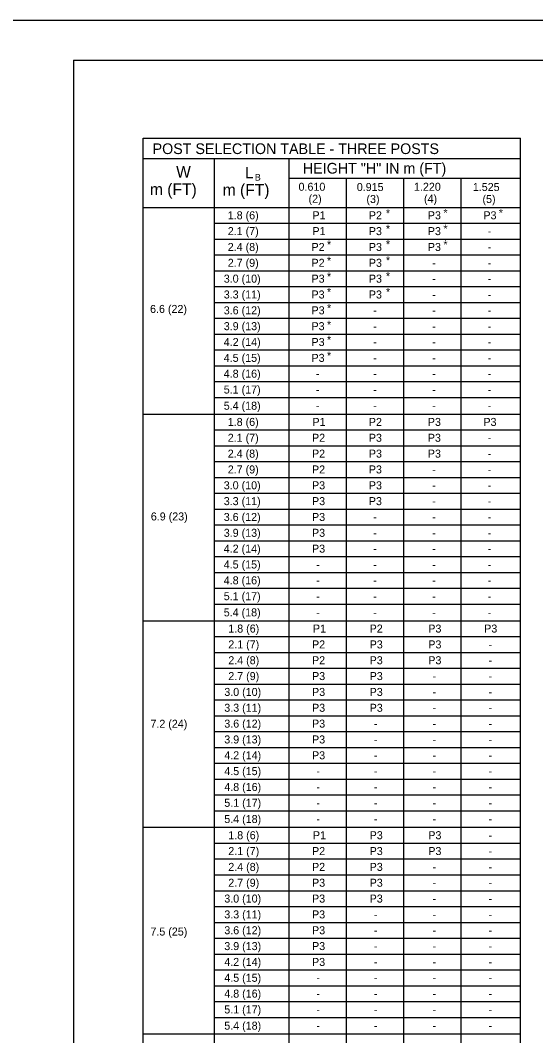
# Model space of a CAD drawing. Extents: x -1958 to 628, y -879 to 309.
# Drawn here: x -256.4 to -63.2, y -71.3 to 309.4 of the extents above; entities that cross this region are included whole.
import ezdxf

# ---------------------------------------------------------------- set-up
doc = ezdxf.new("R2010")
doc.units = 0
for name, color, linetype in [('1', 7, 'Continuous'), ('2', 7, 'Continuous'), ('PLT-BNDY', 7, 'Continuous')]:
    doc.layers.add(name, color=color, linetype=linetype)

msp = doc.modelspace()

# ---------------------------------------------------------------- linework, layer by layer
at = {"layer": '1'}
for p, q in [((-236.39, 294.44), (549.61, 294.44)), ((-236.39, 294.44), (-236.39, -269.56)), ((-210.36, -148.17), (-210.36, 265.3)), ((-210.36, 265.3), (-68.88, 265.3)), ((-68.88, -148.17), (-68.88, 265.3)), ((-210.36, 257.63), (-68.88, 257.63)), ((-183.56, -148.17), (-183.56, 257.63)), ((-155.55, -148.17), (-155.55, 257.63)), ((-134.05, -148.17), (-134.05, 250.28)), ((-112.55, -148.17), (-112.55, 250.28)), ((-91.05, -148.17), (-91.05, 250.28)), ((-210.36, 239.28), (-68.88, 239.28)), ((-210.36, -70.68), (-68.88, -70.68))]:
    msp.add_line(p, q, dxfattribs=at)
at = {"layer": '2'}
for p, q in [((-155.55, 250.28), (-68.88, 250.28)), ((-183.56, 233.34), (-68.88, 233.34)), ((-183.56, 227.4), (-68.88, 227.4)), ((-183.56, 221.46), (-68.88, 221.46)), ((-183.56, 215.52), (-68.88, 215.52)), ((-183.56, 209.58), (-68.88, 209.58)), ((-183.56, 203.64), (-68.88, 203.64)), ((-183.56, 197.7), (-68.88, 197.7)), ((-183.56, 191.76), (-68.88, 191.76)), ((-183.56, 185.82), (-68.88, 185.82)), ((-183.56, 179.88), (-68.88, 179.88)), ((-183.56, 173.94), (-68.88, 173.94)), ((-183.56, 168), (-68.88, 168)), ((-210.36, 161.79), (-68.88, 161.79)), ((-183.56, 155.85), (-68.88, 155.85)), ((-183.56, 149.91), (-68.88, 149.91)), ((-183.56, 143.97), (-68.88, 143.97)), ((-183.56, 138.03), (-68.88, 138.03)), ((-183.56, 132.09), (-68.88, 132.09)), ((-183.56, 126.15), (-68.88, 126.15)), ((-183.56, 120.21), (-68.88, 120.21)), ((-183.56, 114.27), (-68.88, 114.27)), ((-183.56, 108.33), (-68.88, 108.33)), ((-183.56, 102.39), (-68.88, 102.39)), ((-183.56, 96.45), (-68.88, 96.45)), ((-183.56, 90.51), (-68.88, 90.51)), ((-210.36, 84.3), (-68.88, 84.3)), ((-183.56, 78.36), (-68.88, 78.36)), ((-183.56, 72.42), (-68.88, 72.42)), ((-108.57, 72.42), (-72.93, 72.42)), ((-183.56, 66.48), (-68.88, 66.48)), ((-108.57, 66.48), (-72.93, 66.48)), ((-183.56, 60.54), (-68.88, 60.54)), ((-108.57, 60.54), (-72.93, 60.54)), ((-183.56, 54.6), (-68.88, 54.6)), ((-108.57, 54.6), (-72.93, 54.6)), ((-183.56, 48.66), (-68.88, 48.66)), ((-183.56, 42.72), (-68.88, 42.72)), ((-183.56, 36.78), (-68.88, 36.78)), ((-108.57, 36.78), (-72.93, 36.78)), ((-183.56, 30.84), (-68.88, 30.84)), ((-183.56, 24.9), (-68.88, 24.9)), ((-183.56, 18.96), (-68.88, 18.96)), ((-108.57, 18.96), (-72.93, 18.96)), ((-183.56, 13.02), (-68.88, 13.02)), ((-210.36, 6.81), (-68.88, 6.81)), ((-183.56, 0.87), (-68.88, 0.87)), ((-108.57, 0.87), (-72.93, 0.87)), ((-183.56, -5.07), (-68.88, -5.07)), ((-183.56, -11.01), (-68.88, -11.01)), ((-108.57, -11.01), (-72.93, -11.01)), ((-183.56, -16.95), (-68.88, -16.95)), ((-183.56, -22.89), (-68.88, -22.89)), ((-183.56, -28.83), (-68.88, -28.83)), ((-183.56, -34.77), (-68.88, -34.77)), ((-183.56, -40.71), (-68.88, -40.71)), ((-183.56, -46.65), (-68.88, -46.65)), ((-183.56, -52.59), (-68.88, -52.59)), ((-108.57, -52.59), (-72.93, -52.59)), ((-183.56, -58.53), (-68.88, -58.53)), ((-183.56, -64.47), (-68.88, -64.47)), ((-108.57, -64.47), (-72.93, -64.47))]:
    msp.add_line(p, q, dxfattribs=at)
at = {"layer": 'PLT-BNDY'}
msp.add_lwpolyline([(-276.39, 309.44), (564.61, 309.44), (564.61, -284.56), (-276.39, -284.56)], close=True, dxfattribs=at)

# ---------------------------------------------------------------- texts
at = {"layer": '1'}
for s, height, p in [('POST SELECTION TABLE - THREE POSTS', 4.003, (-206.79, 259.28)), ('HEIGHT "H" IN m (FT)', 4.003, (-150.44, 251.96)), ('W', 4.37, (-197.96, 250.43)), ('L', 4.3, (-172.17, 250.16)), ('B', 2.5, (-168.46, 249.33)), ('m (FT)', 4.375, (-207.78, 243.87)), ('m (FT)', 4.375, (-180.51, 243.7)), ('0.610', 3, (-152.07, 245.52)), ('0.915', 3, (-130.23, 245.42)), ('1.220', 3, (-108.78, 245.52)), ('1.525', 3, (-86.73, 245.42)), ('(2)', 3, (-148.32, 241.02)), ('(3)', 3, (-126.61, 240.92)), ('(4)', 3, (-105.03, 241.02)), ('(5)', 3, (-83.11, 240.92))]:
    msp.add_text(s, height=height, dxfattribs=at).set_placement(p)
at = {"layer": '2'}
for s, p in [('1.8 (6)', (-178.61, 234.82)), ('P1', (-146.87, 234.82)), ('P2', (-125.71, 234.82)), ('*', (-119.31, 235.6)), ('P3', (-103.6, 234.82)), ('*', (-97.76, 235.73)), ('P3', (-82.76, 234.82)), ('*', (-77.01, 235.73)), ('*', (-119.31, 229.8)), ('*', (-97.76, 229.8)), ('2.1 (7)', (-178.61, 228.88)), ('P1', (-146.87, 228.88)), ('P3', (-125.71, 228.88)), ('P3', (-103.6, 228.88)), ('-', (-81.14, 228.88)), ('2.4 (8)', (-178.61, 222.94)), ('P2', (-147.21, 222.94)), ('*', (-141.41, 223.87)), ('P3', (-125.71, 222.94)), ('*', (-119.31, 224)), ('P3', (-103.6, 222.94)), ('*', (-97.76, 223.87)), ('*', (-119.31, 217.94)), ('-', (-81.14, 222.94)), ('2.7 (9)', (-178.61, 217)), ('P2', (-147.21, 217)), ('*', (-141.41, 217.8)), ('P3', (-125.71, 217)), ('-', (-101.98, 217)), ('-', (-81.14, 217)), ('3.0 (10)', (-180.11, 211.06)), ('P3', (-147.21, 211.06)), ('*', (-141.41, 211.87)), ('P3', (-125.71, 211.06)), ('*', (-119.31, 212.01)), ('-', (-101.98, 211.06)), ('-', (-81.14, 211.06)), ('3.3 (11)', (-180.11, 205.12)), ('P3', (-147.21, 205.12)), ('*', (-141.41, 206.08)), ('P3', (-125.71, 205.12)), ('*', (-119.31, 206.08)), ('-', (-101.98, 205.12)), ('-', (-81.14, 205.12)), ('6.6 (22)', (-207.74, 199.7)), ('3.6 (12)', (-180.11, 199.18)), ('P3', (-147.21, 199.18)), ('*', (-141.41, 200.01)), ('-', (-124.09, 199.18)), ('-', (-101.98, 199.18)), ('-', (-81.14, 199.18)), ('3.9 (13)', (-180.11, 193.24)), ('P3', (-147.21, 193.24)), ('*', (-141.41, 193.81)), ('-', (-124.09, 193.24)), ('-', (-101.98, 193.24)), ('-', (-81.14, 193.24)), ('4.2 (14)', (-180.11, 187.3)), ('*', (-141.41, 188.15)), ('P3', (-147.21, 187.3)), ('-', (-124.09, 187.3)), ('-', (-101.98, 187.3)), ('-', (-81.14, 187.3)), ('4.5 (15)', (-180.11, 181.36)), ('P3', (-147.21, 181.36)), ('*', (-141.41, 182.22)), ('-', (-124.09, 181.36)), ('-', (-101.98, 181.36)), ('-', (-81.14, 181.36)), ('4.8 (16)', (-180.11, 175.42)), ('-', (-145.6, 175.42)), ('-', (-124.09, 175.42)), ('-', (-101.98, 175.42)), ('-', (-81.14, 175.42)), ('5.1 (17)', (-180.11, 169.48)), ('-', (-145.6, 169.48)), ('-', (-124.09, 169.48)), ('-', (-101.98, 169.48)), ('-', (-81.14, 169.48)), ('5.4 (18)', (-180.11, 163.4)), ('-', (-145.6, 163.4)), ('-', (-124.09, 163.4)), ('-', (-101.98, 163.4)), ('-', (-81.14, 163.4)), ('1.8 (6)', (-178.61, 157.33)), ('P1', (-146.87, 157.33)), ('P2', (-125.71, 157.33)), ('P3', (-103.6, 157.33)), ('P3', (-82.76, 157.33)), ('2.1 (7)', (-178.61, 151.39)), ('P2', (-147.02, 151.39)), ('P3', (-125.71, 151.39)), ('P3', (-103.6, 151.39)), ('-', (-81.15, 151.39)), ('2.4 (8)', (-178.61, 145.45)), ('P2', (-147.02, 145.45)), ('P3', (-125.71, 145.45)), ('P3', (-103.6, 145.45)), ('-', (-81.14, 145.45)), ('2.7 (9)', (-178.61, 139.51)), ('P2', (-147.02, 139.51)), ('P3', (-125.71, 139.51)), ('-', (-101.99, 139.51)), ('-', (-81.14, 139.51)), ('3.0 (10)', (-180.11, 133.57)), ('P3', (-147.02, 133.57)), ('P3', (-125.71, 133.57)), ('-', (-101.99, 133.57)), ('-', (-81.14, 133.57)), ('3.3 (11)', (-180.11, 127.63)), ('P3', (-147.02, 127.63)), ('P3', (-125.71, 127.63)), ('-', (-101.99, 127.63)), ('-', (-81.14, 127.63)), ('6.9 (23)', (-207.45, 121.89)), ('3.6 (12)', (-180.11, 121.69)), ('P3', (-147.02, 121.69)), ('-', (-124.09, 121.69)), ('-', (-101.99, 121.69)), ('-', (-81.14, 121.69)), ('3.9 (13)', (-180.11, 115.75)), ('P3', (-147.02, 115.75)), ('-', (-124.09, 115.75)), ('-', (-101.99, 115.75)), ('-', (-81.14, 115.75)), ('4.2 (14)', (-180.11, 109.81)), ('P3', (-147.02, 109.81)), ('-', (-124.09, 109.81)), ('-', (-101.99, 109.81)), ('-', (-81.14, 109.81)), ('4.5 (15)', (-180.11, 103.87)), ('-', (-145.4, 103.87)), ('-', (-124.09, 103.87)), ('-', (-101.99, 103.87)), ('-', (-81.14, 103.87)), ('4.8 (16)', (-180.11, 97.93)), ('-', (-145.4, 97.93)), ('-', (-124.09, 97.93)), ('-', (-101.99, 97.93)), ('-', (-81.14, 97.93)), ('5.1 (17)', (-180.11, 91.99)), ('-', (-145.4, 91.99)), ('-', (-124.09, 91.99)), ('-', (-101.99, 91.99)), ('-', (-81.14, 91.99)), ('5.4 (18)', (-180.11, 85.91)), ('-', (-145.4, 85.91)), ('-', (-124.09, 85.91)), ('-', (-101.99, 85.91)), ('-', (-81.14, 85.91)), ('1.8 (6)', (-178.41, 79.84)), ('P1', (-146.67, 79.84)), ('P2', (-125.41, 79.84)), ('P3', (-103.42, 79.84)), ('P3', (-82.47, 79.84)), ('2.1 (7)', (-178.41, 73.9)), ('P2', (-147.01, 73.9)), ('P3', (-125.41, 73.9)), ('P3', (-103.42, 73.9)), ('-', (-80.85, 73.9)), ('2.4 (8)', (-178.41, 67.96)), ('P2', (-147.01, 67.96)), ('P3', (-125.41, 67.96)), ('P3', (-103.42, 67.96)), ('-', (-80.85, 67.96)), ('2.7 (9)', (-178.41, 62.02)), ('P3', (-147.01, 62.02)), ('P3', (-125.41, 62.02)), ('-', (-101.81, 62.02)), ('-', (-80.85, 62.02)), ('3.0 (10)', (-179.91, 56.08)), ('P3', (-147.01, 56.08)), ('P3', (-125.41, 56.08)), ('-', (-101.81, 56.08)), ('-', (-80.85, 56.08)), ('3.3 (11)', (-179.91, 50.14)), ('P3', (-147.01, 50.14)), ('P3', (-125.41, 50.14)), ('-', (-101.81, 50.14)), ('-', (-80.85, 50.14)), ('7.2 (24)', (-207.6, 44.14)), ('3.6 (12)', (-179.91, 44.2)), ('P3', (-147.01, 44.2)), ('-', (-123.79, 44.2)), ('-', (-101.81, 44.2)), ('-', (-80.85, 44.2)), ('3.9 (13)', (-179.91, 38.26)), ('P3', (-147.01, 38.26)), ('-', (-123.79, 38.26)), ('-', (-101.81, 38.26)), ('-', (-80.85, 38.26)), ('4.2 (14)', (-179.91, 32.32)), ('P3', (-147.01, 32.32)), ('-', (-123.79, 32.32)), ('-', (-101.81, 32.32)), ('-', (-80.85, 32.32)), ('4.5 (15)', (-179.91, 26.38)), ('-', (-145.39, 26.38)), ('-', (-123.79, 26.38)), ('-', (-101.81, 26.38)), ('-', (-80.85, 26.38)), ('4.8 (16)', (-179.91, 20.44)), ('-', (-145.39, 20.44)), ('-', (-123.79, 20.44)), ('-', (-101.81, 20.44)), ('-', (-80.85, 20.44)), ('5.1 (17)', (-179.91, 14.5)), ('-', (-145.39, 14.5)), ('-', (-123.79, 14.5)), ('-', (-101.81, 14.5)), ('-', (-80.85, 14.5)), ('5.4 (18)', (-179.91, 8.42)), ('-', (-145.39, 8.42)), ('-', (-123.79, 8.42)), ('-', (-101.81, 8.42)), ('-', (-80.85, 8.42)), ('1.8 (6)', (-178.41, 2.35)), ('P1', (-146.67, 2.35)), ('P3', (-125.41, 2.35)), ('P3', (-103.42, 2.35)), ('-', (-80.85, 2.35)), ('2.1 (7)', (-178.41, -3.59)), ('P2', (-147.01, -3.59)), ('P3', (-125.41, -3.59)), ('P3', (-103.42, -3.59)), ('-', (-80.85, -3.59)), ('2.4 (8)', (-178.41, -9.53)), ('P2', (-147.01, -9.53)), ('P3', (-125.41, -9.53)), ('-', (-101.81, -9.53)), ('-', (-80.85, -9.53)), ('2.7 (9)', (-178.41, -15.47)), ('P3', (-147.01, -15.47)), ('P3', (-125.41, -15.47)), ('-', (-101.81, -15.47)), ('-', (-80.85, -15.47)), ('3.0 (10)', (-179.91, -21.41)), ('P3', (-147.01, -21.41)), ('P3', (-125.41, -21.41)), ('-', (-101.81, -21.41)), ('-', (-80.85, -21.41)), ('3.3 (11)', (-179.91, -27.35)), ('P3', (-147.01, -27.35)), ('-', (-123.79, -27.35)), ('-', (-101.81, -27.35)), ('-', (-80.85, -27.35)), ('3.6 (12)', (-179.91, -33.29)), ('P3', (-147.01, -33.29)), ('7.5 (25)', (-207.6, -33.78)), ('-', (-123.79, -33.29)), ('-', (-101.81, -33.29)), ('-', (-80.85, -33.29)), ('3.9 (13)', (-179.91, -39.23)), ('P3', (-147.01, -39.23)), ('-', (-123.79, -39.23)), ('-', (-101.81, -39.23)), ('-', (-80.85, -39.23)), ('4.2 (14)', (-179.91, -45.17)), ('P3', (-147.01, -45.17)), ('-', (-123.79, -45.17)), ('-', (-101.81, -45.17)), ('-', (-80.85, -45.17)), ('4.5 (15)', (-179.91, -51.11)), ('-', (-145.39, -51.11)), ('-', (-123.79, -51.11)), ('-', (-101.81, -51.11)), ('-', (-80.85, -51.11)), ('4.8 (16)', (-179.91, -57.05)), ('-', (-145.39, -57.05)), ('-', (-123.79, -57.05)), ('-', (-101.81, -57.05)), ('-', (-80.85, -57.05)), ('5.1 (17)', (-179.91, -62.99)), ('-', (-145.39, -62.99)), ('-', (-123.79, -62.99)), ('-', (-101.81, -62.99)), ('-', (-80.85, -62.99)), ('5.4 (18)', (-179.91, -69.07)), ('-', (-145.39, -69.07)), ('-', (-123.79, -69.07)), ('-', (-101.81, -69.07)), ('-', (-80.85, -69.07))]:
    msp.add_text(s, height=3, dxfattribs=at).set_placement(p)

doc.saveas('drawing.dxf')
